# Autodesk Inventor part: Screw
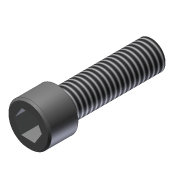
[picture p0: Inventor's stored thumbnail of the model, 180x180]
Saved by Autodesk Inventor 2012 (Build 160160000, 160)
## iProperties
Created: 2006-07
Part Number: Screw
Material: system_material_0
Description: SCREW, CAP, 1/4-20 X 3/8
Document SubType Name: Modeling
Designer: Z.MCGILL
Engineer: SAP
Manufacturer: Standard
Standards Organization: Custom
Mass: 26.2447 g
Surface Area: 18.9522 cm^2
Volume: 3.34682 cm^3
Density: 7.84168 g/cm^3
Author: Z.MCGILL
NetWeight: 0.005
WeightUOM: KG
ModelCode: Comp
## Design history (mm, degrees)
node "SHCS" dims "d23" = 0, "d24" = 0, "Head_Length" = 9.525, "Head_Chamfer" = 0.635, "Head_Diameter" = 14.2875, "Thread_Length" = 31.75, "Hex_Head_Depth" = 7.9375, "Hex_Head_Width" = 7.9375, "Thread_Chamfer" = 0.2286, "Thread_Diameter" = 9.525, "ScaleForDerivedMember" = 10
body "Solid1"
feature "Solid1::SHCS" dims "d23" = 0, "d24" = 0, "Head_Length" = 9.525, "Head_Chamfer" = 0.635, "Head_Diameter" = 14.2875, "Thread_Length" = 31.75, "Hex_Head_Depth" = 7.9375, "Hex_Head_Width" = 7.9375, "Thread_Chamfer" = 0.2286, "Thread_Diameter" = 9.525, "ScaleForDerivedMember" = 10
tag "TaggingFeature1"
